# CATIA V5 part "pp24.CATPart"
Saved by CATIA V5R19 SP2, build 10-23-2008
Part number: pp24
Bounding box of the stored display mesh (mm): x -18 to 18, y -428.399 to -211.601, z 34.146 to 67.997
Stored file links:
  D:\thinkmotion-MPB\Dropbox\Pack 1 sylvain\jlicbarski\thk2\pp24.CATPart
  D:\thinkmotion-MPB\Dropbox\Pack 1 sylvain\jlicbarski\thk2\Brasmeca.CATProduct
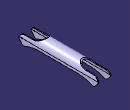
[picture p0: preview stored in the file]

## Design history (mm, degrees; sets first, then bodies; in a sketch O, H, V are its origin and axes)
External parameters (linked from other documents)
  External.Length.4 = 32 mm
  External.Length.3 = 36 mm
  External.Length.2 = 18 mm
  External.Length.1 = 16 mm
  External.Length.5 = 17.604 mm
  External.Length.8 = 6.95 mm
  External.Length.7 = 8.799 mm
  External.Length.6 = 1.601 mm
  External.Length.9 = 1.745 mm
AxisSystem1: origin (0, -320, 0), X (1, 0, 0), Y (0, 1, 0), Z (0, 0, 1)
Set1
  Plane1: linked copy from another document
  Line1: linked copy from another document
  Line2: linked copy from another document
  Sketch1, origin (5, 0, 0), H (0, 1, 0), V (0, 0, 1), geometry linked from another document
Body1 (main body)
  Sketch2 on Plane1, origin (0, -210, 0), H (-1, 0, 0), V (0, 0, 1)
    arc A1 centre (0, 50) radius 16 from (16, 50) to (-16, 50) ccw
    arc A2 centre (0, 50) radius 18 from (18, 50) to (-18, 50) ccw
    reference projected point E1 (0, 50) from Line1
    reference projected point E2 (0, 50) from Line1
    line L1 (16, 50) -> (16, 32.396)
    line L2 (18, 50) -> (18, 32.396)
    line L3 (-18, 50) -> (-18, 32.396)
    line L4 (-16, 50) -> (-16, 32.396)
    line L5 (-18, 32.396) -> (-16, 32.396)
    line L6 (16, 32.396) -> (18, 32.396)
    radius A2 = 18 {= External.Length.3 /2}
    radius A1 = 16 {= External.Length.4 /2}
    distance A2 E1 = 18 {= External.Length.2}
    distance A1 E2 = 16 {= External.Length.1}
    length L2 = 17.604 {= External.Length.5}
    length L1 = 17.604 {= External.Length.5}
    length L4 = 17.604 {= External.Length.5}
    length L3 = 17.604 {= External.Length.5}
  Pad1: profile Sketch2, direction (0, -1, 0), length 220
  Line3: stored without definition
  Sketch3 on face of Pad1 from Sketch2.L3, origin (18, 0, 0), H (0, 1, 0), V (0, 0, 1)
    line L1 (-217.4361, 57.1471) -> (-217.0908, 56.9113)
    line L2 (-213.4395, 52.6413) -> (-211.9795, 49.5658)
    line L3 (-212.2649, 45.7042) -> (-218.8846, 37.5503)
    line L4 (-227.3986, 34.4395) -> (-233.891, 36.9082)
    arc A1 centre (-225.2761, 41.8368) radius 7.6958 from (-227.3986, 34.4395) to (-218.8846, 37.5503) ccw
    arc A2 centre (-215.5181, 47.886) radius 3.9171 from (-211.9795, 49.5658) to (-212.2649, 45.7042) cw
    reference projected line E1 (-210, 32.396) -> (-430, 32.396) from edge [face of Pad1 from Sketch2.L3 | face of Pad1 from Sketch2.L5]
    reference projected line E2 (-210, 50) -> (-210, 32.396) from edge [face of Pad1 from Sketch2.L3 | start face of Pad1]
    arc A3 centre (-223.1559, 48.0288) radius 10.7557 from (-213.4395, 52.6413) to (-217.0908, 56.9113) ccw
    arc A4 centre (-222.7848, 49.3139) radius 9.4851 from (-217.4361, 57.1471) to (-222.7848, 58.799) ccw
    arc A5 centre (-267.3229, -51.0118) radius 94.0618 from (-233.891, 36.9082) to (-267.3229, 43.05) ccw
    line L5 (-264.7739, 63.5348) -> (-272.9456, 68.0239)
    line L6 (-272.9456, 68.0239) -> (-254.3683, 73.9023)
    arc A6 centre (-246.3092, 97.1468) radius 38.3498 from (-246.33, 58.797) to (-264.7739, 63.5348) cw
    line L7 (-245.0795, 58.799) -> (-224.8335, 58.799)
    reference projected line E3 (-210, 50) -> (-430, 50) from edge [face of Pad1 from Sketch2.A2 | face of Pad1 from Sketch2.L3]
    line L8 (-224.8335, 58.799) -> (-222.7848, 58.799)
    line L9 (-245.0795, 58.799) -> (-246.33, 58.797)
    arc A7 centre (-372.6771, -51.0118) radius 94.0618 from (-406.109, 36.9082) to (-372.6771, 43.05) cw
    line L10 (-412.6014, 34.4395) -> (-406.109, 36.9082)
    arc A8 centre (-414.7239, 41.8368) radius 7.6958 from (-412.6014, 34.4395) to (-421.1154, 37.5503) cw
    line L11 (-427.7351, 45.7042) -> (-421.1154, 37.5503)
    arc A9 centre (-424.4819, 47.886) radius 3.9171 from (-428.0205, 49.5658) to (-427.7351, 45.7042) ccw
    line L12 (-426.5605, 52.6413) -> (-428.0205, 49.5658)
    arc A10 centre (-416.8441, 48.0288) radius 10.7557 from (-426.5605, 52.6413) to (-422.9092, 56.9113) cw
    arc A11 centre (-417.2152, 49.3139) radius 9.4851 from (-422.5639, 57.1471) to (-417.2152, 58.799) cw
    line L13 (-394.9205, 58.799) -> (-415.1665, 58.799)
    arc A12 centre (-393.6908, 97.1468) radius 38.3498 from (-393.67, 58.797) to (-375.2261, 63.5348) ccw
    line L14 (-375.2261, 63.5348) -> (-367.0544, 68.0239)
    line L15 (-367.0544, 68.0239) -> (-385.6317, 73.9023)
    line L16 (-394.9205, 58.799) -> (-393.67, 58.797)
    line L17 (-422.5639, 57.1471) -> (-422.9092, 56.9113)
    line L18 (-254.3683, 73.9023) -> (-187.259, 76.5052)
    line L19 (-187.259, 76.5052) -> (-205.5646, 4.4149)
    line L20 (-205.5646, 4.4149) -> (-452.3486, 13.3081)
    line L21 (-452.3486, 13.3081) -> (-447.0434, 76.9649)
    line L22 (-447.0434, 76.9649) -> (-385.6317, 73.9023)
    line L23 (-415.1665, 58.799) -> (-417.2152, 58.799)
    line L24 (-267.3229, 43.05) -> (-372.6771, 43.05)
    distance A1 E1 = 1.745 {= External.Length.9}
    distance A2 E2 = 1.601 {= External.Length.6}
    distance L7 E3 = 8.799 {= External.Length.7}
    distance L13 E3 = 8.799
    distance A8 E1 = 1.745
  Pocket1: profile Sketch3, direction (-1, 0, 0), length 220
  Sketch4 on face of Pad1 from Sketch2.L4, origin (16, 0, 0), H (0, -1, 0), V (0, 0, 1)
    circle A1 centre (420, 50) radius 2
    reference projected point E1 (420, 50) from Line2
    distance A1 E1 = 2
    radius A1 = 2
  Pocket2: profile Sketch4, direction (1, 0, 0), length 220
  Pocket3: profile Sketch1, direction (-1, 0, 0), length 220
  Pocket4: profile Sketch1, direction (1, 0, 0), length 220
